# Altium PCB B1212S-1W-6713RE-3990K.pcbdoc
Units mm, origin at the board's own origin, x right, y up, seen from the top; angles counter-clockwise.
Board outline 11.8 x 10.32 mm, 2 copper layers (Top Layer, Bottom Layer), stack 0.78 mm thick; 9 components, 9 nets, 30 pads, 6 vias.
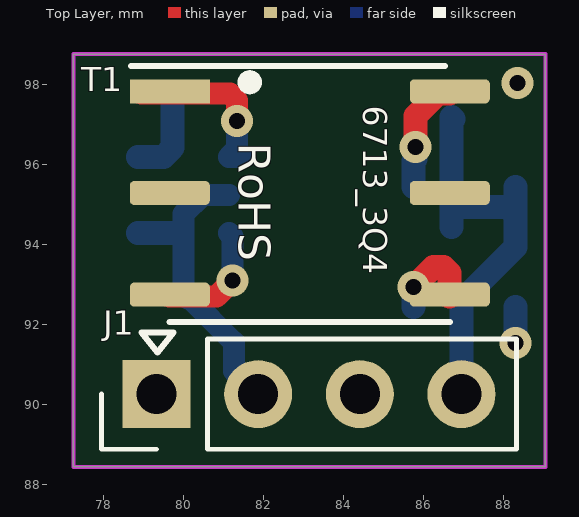
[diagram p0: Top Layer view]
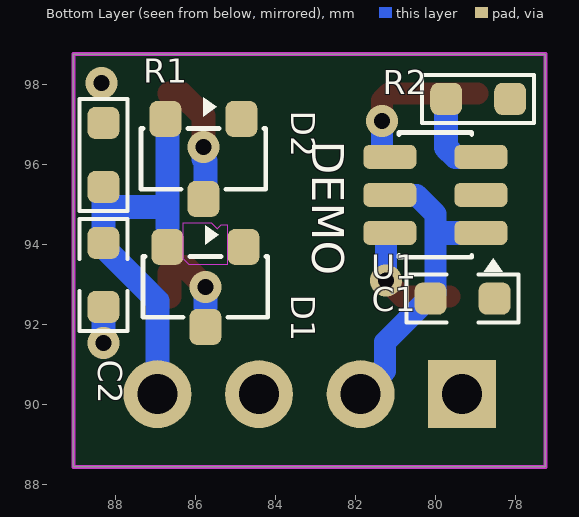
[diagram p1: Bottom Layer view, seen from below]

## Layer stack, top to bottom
Top Solder Mask Layer: solder mask 0.01, Dk 0
Top Layer: signal copper 0.035
dielectric 1: surface 0.71, FR4, Dk 4.5
Bottom Layer: signal copper 0.035
Bottom Solder Mask Layer: solder mask 0.01, Dk 0

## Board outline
77.25,98.771 89.05,98.771 89.05,88.451 77.25,88.451

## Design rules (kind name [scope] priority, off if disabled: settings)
BoardOutlineClearance copperThickness1oz [All] p0: genericclearance=0.254 ignorepadtopadclearanceinfootprint=FALSE except(0: Arc-SplitContinuation Track-SplitContinuation SMDPad-SplitContinuation THPad-SplitContinuation Via-SplitContinuation Fill-SplitContinuation Poly-SplitContinuation Region-SplitContinuation Text-SplitContinuation)
BoardOutlineClearance otherClearance [All] p0: genericclearance=0.254 ignorepadtopadclearanceinfootprint=FALSE except(0: Arc-SplitContinuation Track-SplitContinuation SMDPad-SplitContinuation THPad-SplitContinuation Via-SplitContinuation Fill-SplitContinuation Poly-SplitContinuation Region-SplitContinuation Text-SplitContinuation)
Clearance copperThickness1oz [All] p1: gap=0.178 ignorepadtopadclearanceinfootprint=FALSE
Clearance otherClearance [All] p1: gap=0.178 ignorepadtopadclearanceinfootprint=FALSE
DiffPairsRouting differentialPair [All] p1: maxuncoupledlength=10 minlimit=5 maxlimit=Infinity mostfreqgap=6 toplayer_minwidth=5 toplayer_prefwidth=100 toplayer_maxwidth=100 bottomlayer_minwidth=5 bottomlayer_prefwidth=100 bottomlayer_maxwidth=100
PasteMaskExpansion pasteMaskExpansion [All] p1: expansion=0
PlaneConnect innerPlane [All] p1: planeconnectstyle=Relief reliefexpansion=0.508 reliefentries=4 reliefconductorwidth=0.254 reliefairgap=0.254
PolygonConnect copper0 [All] p1: connectstyle=Direct reliefentries=4 reliefconductorwidth=10 polygonreliefangle="90 Angle" airgapwidth=10
RoutingVias viaSize [All] p1: viastyle="Through Hole" holewidth=24 minholewidth=11.811 maxholewidth=393.7 width=24 minwidth=11.811 maxwidth=393.7
SolderMaskExpansion solderMaskExpansion [All] p1: useseparateexpansions=TRUE expansion=2 expansionbottom=2
Width copperThickness1oz [All] p1: maxlimit=100 minlimit=5 preferedwidth=10

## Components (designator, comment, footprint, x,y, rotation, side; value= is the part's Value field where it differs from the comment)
C1 "10uF" C0805 79.32,92.661 r0 bottom
C2 "10uF" C0805 88.3,93.251 r90 bottom
D1 "Diode_BAS40-04" MYLibrary:SOT-23 85.75,92.951 r270 bottom
D2 "Diode_BAS40-04" MYLibrary:SOT-23 85.8,96.151 r270 bottom
J1 "PZ2.54-1*4-WZ" HDR-TH_4P-P2.54-H-M-W7.7-P 79.32,90.251 r90 top
R1 "10kΩ" R0603 88.3,96.251 r90 bottom
R2 "15kΩ" R0603 78.93,97.651 r0 bottom
T1 "" ? 83.16,95.299 r0 top
U1 "CMP6713RE" SOT-23-6_L2.9-W1.6-P0.95-LS2.8-BL-2 80,95.251 r0 bottom

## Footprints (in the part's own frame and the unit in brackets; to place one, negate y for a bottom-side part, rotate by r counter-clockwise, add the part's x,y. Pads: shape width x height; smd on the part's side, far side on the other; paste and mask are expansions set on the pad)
C0805 [mm]
  rrect50% 0.8x0.8 smd: 1(-0.8,0) 2(0.8,0)
  silkscreen extent -1.4,-0.6 1.4,0.6
HDR-TH_4P-P2.54-H-M-W7.7-P [mm]
  rect 1.7x1.7 hole 1: 1(0.02,-0.01)
  round 1.7 hole 1: 2(0.02,-2.55) 3(0.02,-5.09) 4(0.02,-7.63)
  silkscreen extent -1.36,-9.01 1.4,1.37
MYLibrary:SOT-23 [mm]
  rrect50% 0.9x0.8 smd: 1(-1,0.95) 2(-1,-0.95) 3(1,0)
  silkscreen extent -1.54,-1.56 0.76,1.56
R0603 [mm]
  rrect50% 0.8x0.8 smd: 1(-0.8,0) 2(0.8,0)
  silkscreen extent -1.4,-0.6 1.4,0.6
SOT-23-6_L2.9-W1.6-P0.95-LS2.8-BL-2 [mm]
  rrect50% 1.325x0.6 smd: 1(-1.138,0.95) 2(-1.138,0) 3(-1.138,-0.95) 4(1.138,-0.95) 5(1.138,0) 6(1.138,0.95)
  silkscreen extent -1.69,-1.56 0.91,1.92
? [mm]
  rect 2x0.6 smd: 1(-3.5,2.54)
  rrect37% 2x0.6 smd: 2(-3.5,0) 3(-3.5,-2.54) 4(3.5,-2.54) 5(3.5,0) 6(3.5,2.54)
  silkscreen extent -4.46,-3.23 3.5,3.17

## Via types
v1: diameter 0.8, hole 0.4, Top Layer to Bottom Layer, 6 vias

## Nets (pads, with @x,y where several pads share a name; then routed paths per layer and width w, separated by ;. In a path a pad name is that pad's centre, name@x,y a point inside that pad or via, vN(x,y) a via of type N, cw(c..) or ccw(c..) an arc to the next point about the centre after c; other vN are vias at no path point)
0V: C2.1 D1.1 D2.1 J1.3 R1.2 | length 1
  Bottom Layer w0.6: v1@88.3,91.451 v1(88.3,91.551) C2.1
  other v1: 88.35,98.051
$1N6: D1.3 T1.4 | length 2.3
  Top Layer w0.6: v1(85.75,92.951) 86.25,93.451 86.5,93.451 86.65,93.301 T1.4@86.65,92.711
  Bottom Layer w0.6: 85.75,92.451 v1(85.75,92.951)
$1N10: D2.3 T1.6 | length 2.9
  Top Layer w0.6: v1(85.8,96.451) 85.8,97.225 86.366,97.791 T1.6@86.65,97.791
  Bottom Layer w0.6: D2.3@85.75,95.451 85.75,96.101 85.8,96.151 v1(85.8,96.451)
$1N12: R2.2 U1.3 | length 2.2
  Bottom Layer w0.6: U1.3 79.5,96.201 79.73,96.431 R2.2
+VO: C2.2 D1.2 D2.2 J1.4 R1.1 | length 10.9
  Bottom Layer w0.6: J1.4@86.57,90.651 J1.4 86.95,92.601 88.3,93.951 C2.2 88.3,94.751 ; 86.7,94.451 86.7,94.951 ; D2.2@86.7,97.151 86.7,95.451 86.7,94.951 ; D2.2@86.7,97.201 D2.2 ; J1.4@86.94,90.251 J1.4@87.14,90.251 ; R1.1 88.3,94.751 ; 86.7,94.951 88.1,94.951 88.3,94.751
GND: C1.1 J1.1 R2.1 U1.2 | length 0.2
  Top Layer w0.55: J1.1@79.32,90.171 J1.1@79.32,90.251
  Bottom Layer w0.55: J1.1@79.2,90.251 J1.1@79.32,90.251
VD1: T1.3 U1.6 | length 3
  Top Layer w0.55: T1.3@79.65,92.711 80.83,92.711 v1(81.23,93.111)
  Bottom Layer w0.55: U1.6 81.23,94.209 v1(81.23,93.111)
VD2: T1.1 U1.4 | length 4.3
  Top Layer w0.55: T1.1@78.95,97.791 81.16,97.791 81.34,97.611 v1(81.34,97.101)
  Bottom Layer w0.55: U1.4 81.34,96.404 v1(81.34,97.101) ; U1.4@81.15,96.201 U1.4@81.475,96.201
VIN: C1.2 J1.2 U1.1 U1.5 | length 8.7
  Bottom Layer w0.55: U1.5 80.475,95.251 79.999,94.775 79.999,92.782 C1.2 80.17,92.661 81.26,91.571 81.26,90.851 J1.2@81.86,90.251 ; J1.2@81.86,90.616 J1.2@81.86,90.251 ; J1.2@82.126,90.317 81.86,90.051 J1.2@81.86,90.251
  Bottom Layer w0.6: U1.1 79.954,94.301
pads on no net: T1.2 T1.5

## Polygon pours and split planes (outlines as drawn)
0V on Top Layer (solid, remove dead copper, pour order 2): 83.7,91.951 83.86,92.111 87.95,92.111 87.95,98.751 88.9,98.751 89.4,98.251 89.4,89.451 83.7,89.451
0V on Bottom Layer (solid, remove dead copper, pour order 10): 83.9,88.551 83.9,98.851 89,98.851 89.2,98.651 89.2,96.551 89.1,96.451 87.85,96.451 87.6,96.701 87.6,97.651 87.4,97.851 85.5,97.851 85.2,97.551 85.2,88.551
GND on Bottom Layer (solid, remove dead copper, pour order 12): 80.18,88.151 76.7,88.151 76.2,88.651 76.2,97.951 76.5,98.251 78.4,98.251 78.7,97.951 78.7,97.021 78.53,96.851 78,96.851 77.9,96.751 77.9,95.851 78.2,95.551 79.525,95.551 79.525,94.951 78.1,94.951 77.9,94.751 77.9,93.751 78,93.651 78.9,93.651 79.2,93.351 79.2,91.851 79.7,91.351 80,91.351 80.18,91.171
$1N6 on Top Layer (solid, remove dead copper, pour order 8): 85.3,93.851 87.65,93.851 87.65,92.411 85.3,92.411
$1N10 on Top Layer (solid, remove dead copper, pour order 10): 85.4,98.091 87.65,98.091 87.65,96.051 85.4,96.051

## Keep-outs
Bottom Layer:
  region: 85.2,94.501 85.2,93.501 86.15,93.501 86.3,93.651 86.3,94.551 85.6,94.551 85.45,94.401 85.35,94.501
Board Outline Layer:
  the board outline again, w0.1

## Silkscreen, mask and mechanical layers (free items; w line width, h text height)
Top Silkscreen Layer:
  lines w0.15: 78.95,91.811 79.75,91.811 79.35,91.311 78.95,91.811
  text "6713_3Q4" at 84.5,97.477 h0.6 r270
  text "RoHS" at 81.381,96.551 h0.8 r270
Bottom Silkscreen Layer:
  text "DEMO" at 83.079,96.601 h0.8 r90
User.Eco1:
